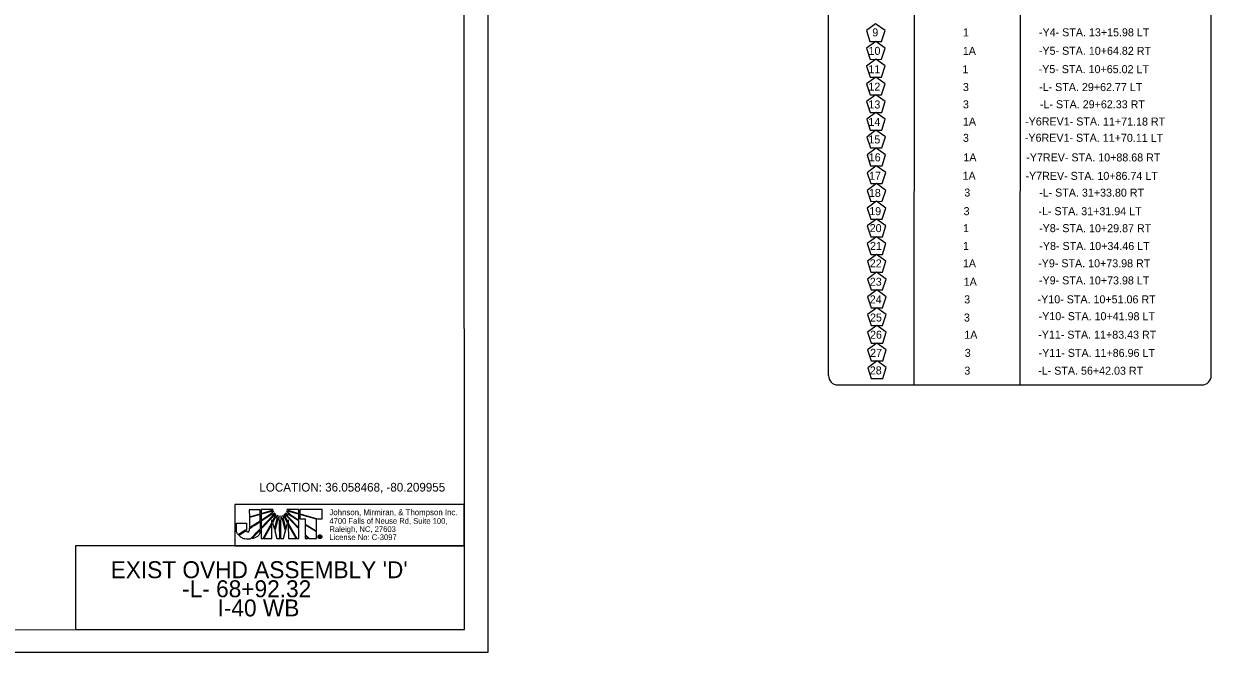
# Model space of a CAD drawing. Extents: x 1726582 to 1728895, y 538986 to 541550.
# Drawn here: x 1727860 to 1728895, y 538986 to 539534 of the extents above; entities that cross this region are included whole.
import ezdxf

# ---------------------------------------------------------------- set-up
doc = ezdxf.new("R2010")
doc.units = 0
for name, color, linetype in [('Default', 7, 'Continuous'), ('DEV BORDER CELL', 7, 'Continuous'), ('GSDIMS', 7, 'Continuous'), ('GSSHT', 7, 'Continuous'), ('Old_Level_7', 7, 'Continuous'), ('Sheet Plot Border Outside CELL', 7, 'Continuous'), ('Sheet Sticker Exception Certification CELL', 7, 'Continuous'), ('Sheet Title CELL', 7, 'Continuous')]:
    doc.layers.add(name, color=color, linetype=linetype)

msp = doc.modelspace()

# ---------------------------------------------------------------- linework, layer by layer
at = {"layer": 'Default'}
for p, q in [((1728636.1, 539699.3), (1728636, 539218.9)), ((1728728.5, 539699.3), (1728728.4, 539218.9)), ((1728066, 539110.2), (1728056.6, 539110.2)), ((1728056.6, 539110.2), (1728056.7, 539104)), ((1728056.7, 539104), (1728066, 539106.6)), ((1728066, 539105.9), (1728056.7, 539103.3)), ((1728066, 539106.6), (1728066, 539110.2)), ((1728066, 539100.5), (1728066, 539105.9)), ((1728077.5, 539110.3), (1728067, 539110.3)), ((1728067, 539110.3), (1728067, 539106.9)), ((1728067, 539106.9), (1728074.8, 539109.1)), ((1728074.8, 539108.4), (1728067, 539106.2)), ((1728067, 539106.2), (1728067, 539101.1)), ((1728067, 539101.1), (1728074, 539105.6)), ((1728075.1, 539105.5), (1728067, 539100.3)), ((1728067, 539094.5), (1728076.9, 539104.8)), ((1728077.3, 539104.3), (1728067, 539093.5)), ((1728074, 539105.6), (1728077.9, 539108.8)), ((1728074.8, 539109.1), (1728077.5, 539110.3)), ((1728077.9, 539108.8), (1728074.8, 539108.4)), ((1728078.7, 539107.3), (1728075.1, 539105.5)), ((1728076.9, 539104.8), (1728078.7, 539107.3)), ((1728079.7, 539106.2), (1728077.3, 539104.3)), ((1728078.6, 539103.2), (1728079.7, 539106.2)), ((1728081.1, 539105.3), (1728079.2, 539103)), ((1728080.8, 539102.5), (1728081.1, 539105.3)), ((1728082.6, 539104.9), (1728081.4, 539101.9)), ((1728083, 539097.5), (1728082.6, 539104.9)), ((1728084.2, 539104.9), (1728083.7, 539097.5)), ((1728085.4, 539101.9), (1728084.2, 539104.9)), ((1728085.7, 539105.3), (1728086, 539102.4)), ((1728087.5, 539103), (1728085.7, 539105.3)), ((1728087, 539106.2), (1728088.2, 539103.2)), ((1728089.5, 539104.3), (1728087, 539106.2)), ((1728088.1, 539107.3), (1728089.9, 539104.7)), ((1728091.7, 539105.5), (1728088.1, 539107.3)), ((1728088.9, 539108.8), (1728092.8, 539105.6)), ((1728091.8, 539108.4), (1728088.9, 539108.8)), ((1728099.8, 539110.3), (1728089.4, 539110.3)), ((1728089.4, 539110.3), (1728092.1, 539109.1)), ((1728099.8, 539093.4), (1728089.5, 539104.3)), ((1728089.9, 539104.7), (1728099.8, 539094.4)), ((1728099.8, 539100.4), (1728091.7, 539105.5)), ((1728099.8, 539106.2), (1728091.8, 539108.4)), ((1728092.1, 539109.1), (1728099.8, 539106.9)), ((1728092.8, 539105.6), (1728099.8, 539101.2)), ((1728099.8, 539106.9), (1728099.8, 539110.3)), ((1728099.8, 539101.2), (1728099.8, 539106.2)), ((1728120.2, 539110.3), (1728100.6, 539110.3)), ((1728100.6, 539110.3), (1728100.6, 539106.7)), ((1728100.6, 539106.7), (1728100.6, 539106.6)), ((1728100.6, 539106.6), (1728116.1, 539102.3)), ((1728100.6, 539106), (1728100.6, 539106)), ((1728100.6, 539106), (1728100.6, 539102.2)), ((1728115.1, 539101.9), (1728100.6, 539106)), ((1728120.2, 539102.3), (1728120.2, 539110.3)), ((1728056.7, 539103.3), (1728056.7, 539094.6)), ((1728056.7, 539094.6), (1728066, 539100.5)), ((1728067, 539100.3), (1728067, 539094.5)), ((1728067, 539093.5), (1728067, 539085)), ((1728068.6, 539085), (1728076.2, 539098.8)), ((1728076.2, 539097.5), (1728069.3, 539085)), ((1728076.2, 539098.8), (1728076.2, 539101.3)), ((1728076.2, 539101.3), (1728076.6, 539099.6)), ((1728076.3, 539085), (1728076.2, 539097.5)), ((1728076.6, 539099.6), (1728078.6, 539103.2)), ((1728079.2, 539103), (1728076.9, 539098.7)), ((1728076.9, 539098.7), (1728078.4, 539093.1)), ((1728078.4, 539093.1), (1728080.8, 539102.5)), ((1728081.4, 539101.9), (1728078.7, 539091.8)), ((1728083.1, 539085.1), (1728083, 539097.5)), ((1728083.7, 539097.5), (1728083.7, 539085.1)), ((1728088.1, 539091.7), (1728085.4, 539101.9)), ((1728086, 539102.4), (1728088.4, 539092.9)), ((1728089.9, 539098.6), (1728087.5, 539103)), ((1728088.2, 539103.2), (1728090.2, 539099.5)), ((1728088.4, 539092.9), (1728089.9, 539098.6)), ((1728090.2, 539099.5), (1728090.6, 539101.3)), ((1728090.6, 539101.3), (1728090.6, 539098.6)), ((1728090.6, 539098.6), (1728098.1, 539085)), ((1728097.4, 539085.1), (1728090.6, 539097.2)), ((1728090.6, 539097.2), (1728090.7, 539085.1)), ((1728099.8, 539094.4), (1728099.8, 539100.4)), ((1728099.8, 539085), (1728099.8, 539093.4)), ((1728100.6, 539102.2), (1728105.4, 539102.2)), ((1728105.4, 539102.2), (1728105.4, 539097.7)), ((1728105.4, 539097.7), (1728115.1, 539091.6)), ((1728105.4, 539096.9), (1728105.4, 539088.6)), ((1728115.1, 539090.9), (1728105.4, 539096.9)), ((1728115.1, 539091.6), (1728115.1, 539101.9)), ((1728116.1, 539102.3), (1728120.2, 539102.3)), ((1728067, 539085), (1728068.6, 539085)), ((1728069.3, 539085), (1728076.3, 539085)), ((1728078.7, 539091.8), (1728080.5, 539085.1)), ((1728080.5, 539085.1), (1728083.1, 539085.1)), ((1728083.7, 539085.1), (1728086.3, 539085.1)), ((1728086.3, 539085.1), (1728088.1, 539091.7)), ((1728090.7, 539085.1), (1728097.4, 539085.1)), ((1728098.1, 539085), (1728099.8, 539085)), ((1728105.4, 539088.6), (1728108.7, 539085)), ((1728107.8, 539085), (1728105.4, 539087.7)), ((1728105.4, 539087.7), (1728105.4, 539085)), ((1728105.4, 539085), (1728107.8, 539085)), ((1728108.7, 539085), (1728115.1, 539085)), ((1728115.1, 539085), (1728115.1, 539090.9)), ((1728117.5, 539085.9), (1728117.5, 539087.4)), ((1728117.5, 539087.4), (1728118.1, 539087.4)), ((1728117.9, 539085.9), (1728117.5, 539085.9)), ((1728118.1, 539087.1), (1728117.9, 539087.1)), ((1728117.9, 539087.1), (1728117.9, 539086.8)), ((1728117.9, 539086.8), (1728118.1, 539086.8)), ((1728118.1, 539086.5), (1728117.9, 539086.5)), ((1728117.9, 539086.5), (1728117.9, 539085.9)), ((1728118.1, 539088.2), (1728118.1, 539087.9)), ((1728118.1, 539087.9), (1728118.1, 539088.2)), ((1728118.1, 539087.4), (1728118.1, 539087.1)), ((1728118.1, 539087.1), (1728118.1, 539087.4)), ((1728118.1, 539087.4), (1728118.2, 539087.4)), ((1728118.2, 539087.1), (1728118.1, 539087.1)), ((1728118.1, 539086.8), (1728118.1, 539086.5)), ((1728118.1, 539086.5), (1728118.1, 539086.8)), ((1728118.1, 539086.8), (1728118.1, 539086.8)), ((1728118.1, 539086.5), (1728118.1, 539086.5)), ((1728118.1, 539085.4), (1728118.1, 539085.1)), ((1728118.1, 539085.1), (1728118.1, 539085.4)), ((1728118.1, 539085.4), (1728118.1, 539085.4)), ((1728118.1, 539085.1), (1728118.1, 539085.1))]:
    msp.add_line(p, q, dxfattribs=at)
for points in [[(1728602.6, 539533.7), (1728594.5, 539527.7), (1728597.6, 539518.2), (1728607.7, 539518.2), (1728610.8, 539527.8)], [(1728602.7, 539518.2), (1728594.6, 539512.3), (1728597.7, 539502.7), (1728607.7, 539502.8), (1728610.8, 539512.3)], [(1728602.7, 539502.8), (1728594.6, 539496.8), (1728597.7, 539487.3), (1728607.8, 539487.3), (1728610.9, 539496.9)], [(1728602.8, 539487.3), (1728594.7, 539481.4), (1728597.8, 539471.8), (1728607.8, 539471.9), (1728610.9, 539481.4)], [(1728602.8, 539471.8), (1728594.7, 539465.9), (1728597.9, 539456.4), (1728607.9, 539456.4), (1728611, 539466)], [(1728602.9, 539456.4), (1728594.8, 539450.5), (1728597.9, 539440.9), (1728607.9, 539440.9), (1728611, 539450.5)], [(1728602.9, 539440.9), (1728594.8, 539435), (1728598, 539425.5), (1728608, 539425.5), (1728611.1, 539435.1)], [(1728603.2, 539425.3), (1728595.1, 539419.4), (1728598.2, 539409.9), (1728608.2, 539409.9), (1728611.3, 539419.5)], [(1728603.2, 539409.9), (1728595.1, 539403.9), (1728598.3, 539394.4), (1728608.3, 539394.4), (1728611.4, 539404)], [(1728603.3, 539394.4), (1728595.2, 539388.5), (1728598.3, 539378.9), (1728608.4, 539379), (1728611.4, 539388.5)], [(1728603.3, 539379), (1728595.2, 539373), (1728598.4, 539363.5), (1728608.4, 539363.5), (1728611.5, 539373.1)], [(1728603.4, 539363.5), (1728595.3, 539357.6), (1728598.4, 539348), (1728608.5, 539348.1), (1728611.5, 539357.6)], [(1728603.4, 539348), (1728595.3, 539342.1), (1728598.5, 539332.6), (1728608.5, 539332.6), (1728611.6, 539342.2)], [(1728603.5, 539332.6), (1728595.4, 539326.7), (1728598.5, 539317.1), (1728608.6, 539317.1), (1728611.6, 539326.7)], [(1728603.5, 539317.1), (1728595.4, 539311.2), (1728598.6, 539301.7), (1728608.6, 539301.7), (1728611.7, 539311.2)], [(1728603.6, 539301.7), (1728595.5, 539295.7), (1728598.6, 539286.2), (1728608.7, 539286.2), (1728611.7, 539295.8)], [(1728603.6, 539286.2), (1728595.5, 539280.3), (1728598.7, 539270.7), (1728608.7, 539270.8), (1728611.8, 539280.3)], [(1728603.7, 539270.8), (1728595.6, 539264.8), (1728598.7, 539255.3), (1728608.8, 539255.3), (1728611.8, 539264.9)], [(1728603.7, 539255.3), (1728595.6, 539249.4), (1728598.8, 539239.8), (1728608.8, 539239.9), (1728611.9, 539249.4)], [(1728603.8, 539239.8), (1728595.7, 539233.9), (1728598.8, 539224.4), (1728608.9, 539224.4), (1728611.9, 539234)], [(1728044, 539078.6), (1728244, 539078.6), (1728244, 539114.7), (1728044, 539114.7)]]:
    msp.add_lwpolyline(points, close=True, dxfattribs=at)
for points in [[(1728056.7, 539104), (1728066, 539106.6), (1728066, 539110.2), (1728056.6, 539110.2), (1728056.7, 539104)], [(1728056.7, 539094.6), (1728066, 539100.5), (1728066, 539105.9), (1728056.7, 539103.3), (1728056.7, 539094.6)], [(1728074.8, 539109.1), (1728077.5, 539110.3), (1728067, 539110.3), (1728067, 539106.9), (1728074.8, 539109.1)], [(1728067, 539106.2), (1728067, 539101.1), (1728074, 539105.6), (1728077.9, 539108.8), (1728074.8, 539108.4), (1728067, 539106.2)], [(1728067, 539100.3), (1728067, 539094.5), (1728076.9, 539104.8), (1728078.7, 539107.3), (1728075.1, 539105.5), (1728067, 539100.3)], [(1728079.7, 539106.2), (1728077.3, 539104.3), (1728067, 539093.5), (1728067, 539085), (1728068.6, 539085), (1728076.2, 539098.8), (1728076.2, 539101.3), (1728076.6, 539099.6), (1728078.6, 539103.2), (1728079.7, 539106.2)], [(1728081.1, 539105.3), (1728079.2, 539103), (1728076.9, 539098.7), (1728078.4, 539093.1), (1728080.8, 539102.5), (1728081.1, 539105.3)], [(1728081.4, 539101.9), (1728078.7, 539091.8), (1728080.5, 539085.1), (1728083.1, 539085.1), (1728083, 539097.5), (1728082.6, 539104.9), (1728081.4, 539101.9)], [(1728084.2, 539104.9), (1728083.7, 539097.5), (1728083.7, 539085.1), (1728086.3, 539085.1), (1728088.1, 539091.7), (1728085.4, 539101.9), (1728084.2, 539104.9)], [(1728085.7, 539105.3), (1728086, 539102.4), (1728088.4, 539092.9), (1728089.9, 539098.6), (1728087.5, 539103), (1728085.7, 539105.3)], [(1728087, 539106.2), (1728088.2, 539103.2), (1728090.2, 539099.5), (1728090.6, 539101.3), (1728090.6, 539098.6), (1728098.1, 539085), (1728099.8, 539085), (1728099.8, 539093.4), (1728089.5, 539104.3), (1728087, 539106.2)], [(1728088.1, 539107.3), (1728089.9, 539104.7), (1728099.8, 539094.4), (1728099.8, 539100.4), (1728091.7, 539105.5), (1728088.1, 539107.3)], [(1728088.9, 539108.8), (1728092.8, 539105.6), (1728099.8, 539101.2), (1728099.8, 539106.2), (1728091.8, 539108.4), (1728088.9, 539108.8)], [(1728092.1, 539109.1), (1728099.8, 539106.9), (1728099.8, 539110.3), (1728089.4, 539110.3), (1728092.1, 539109.1)], [(1728120.2, 539110.3), (1728100.6, 539110.3), (1728100.6, 539106.7), (1728100.6, 539106.6), (1728116.1, 539102.3), (1728120.2, 539102.3), (1728120.2, 539110.3)], [(1728100.6, 539106), (1728100.6, 539106), (1728100.6, 539102.2), (1728105.4, 539102.2), (1728105.4, 539097.7), (1728115.1, 539091.6), (1728115.1, 539101.9), (1728100.6, 539106)], [(1728069.3, 539085), (1728076.3, 539085), (1728076.2, 539097.5), (1728069.3, 539085)], [(1728090.7, 539085.1), (1728097.4, 539085.1), (1728090.6, 539097.2), (1728090.7, 539085.1)], [(1728105.4, 539096.9), (1728105.4, 539088.6), (1728108.7, 539085), (1728115.1, 539085), (1728115.1, 539090.9), (1728105.4, 539096.9), (1728105.4, 539096.9)], [(1728105.4, 539085), (1728105.4, 539085), (1728107.8, 539085), (1728105.4, 539087.7), (1728105.4, 539085)], [(1728118.8, 539086.3), (1728118.8, 539086.2), (1728118.8, 539086.1), (1728118.8, 539086.1), (1728118.8, 539085.9), (1728118.5, 539085.9)]]:
    msp.add_lwpolyline(points, dxfattribs=at)
for points, degree in [([(1728054, 539098.6), (1728054, 539098.6), (1728045.3, 539098.6), (1728045.3, 539098.6), (1728045.3, 539098.6), (1728045.3, 539093.2), (1728045.3, 539093.2), (1728045.3, 539093.2), (1728045.3, 539092.6), (1728045.3, 539092.6), (1728045.3, 539090.9), (1728045.9, 539089.6), (1728046.9, 539088.4), (1728046.9, 539088.4), (1728054, 539092.8), (1728054, 539092.9), (1728054, 539092.9), (1728054, 539098.6), (1728054, 539098.6)], 3), ([(1728055.3, 539090.8), (1728054.8, 539090.8), (1728054.3, 539091.1), (1728054.1, 539092.1), (1728054.1, 539092.1), (1728047.4, 539088), (1728047.4, 539088), (1728049.4, 539085.8), (1728052.7, 539084.5), (1728055.5, 539084.5), (1728056.3, 539084.5), (1728056.8, 539084.6), (1728057.6, 539084.7), (1728057.6, 539084.7), (1728066, 539093.5), (1728066, 539093.5), (1728066, 539093.5), (1728066, 539099.8), (1728066, 539099.8), (1728066, 539099.8), (1728056.7, 539093.8), (1728056.7, 539093.8), (1728056.7, 539091.4), (1728056.1, 539090.8), (1728055.3, 539090.8)], 3), ([(1728055.3, 539090.8), (1728054.8, 539090.8), (1728054.3, 539091.1), (1728054.1, 539092.1), (1728054.1, 539092.1), (1728047.4, 539088), (1728047.4, 539088), (1728049.4, 539085.8), (1728052.7, 539084.5), (1728055.5, 539084.5), (1728056.3, 539084.5), (1728056.8, 539084.6), (1728057.6, 539084.7), (1728057.6, 539084.7), (1728066, 539093.5), (1728066, 539093.5), (1728066, 539093.5), (1728066, 539099.8), (1728066, 539099.8), (1728066, 539099.8), (1728056.7, 539093.8), (1728056.7, 539093.8), (1728056.7, 539091.4), (1728056.1, 539090.8), (1728055.3, 539090.8)], 3), ([(1728066, 539092.5), (1728066, 539092.5), (1728058.7, 539084.9), (1728058.7, 539084.9), (1728062.3, 539085.8), (1728065.9, 539088.2), (1728066, 539092.5)], 3), ([(1728118.1, 539085.1), (1728117.7, 539085.1), (1728117.3, 539085.2), (1728117, 539085.5), (1728116.7, 539085.8), (1728116.5, 539086.2), (1728116.5, 539086.6), (1728116.5, 539087.1), (1728116.7, 539087.5), (1728117, 539087.8), (1728117.3, 539088.1), (1728117.7, 539088.2), (1728118.1, 539088.2)], 3), ([(1728118.1, 539087.9), (1728117.8, 539087.9), (1728117.5, 539087.8), (1728117.2, 539087.6), (1728117, 539087.3), (1728116.9, 539087), (1728116.9, 539086.6), (1728116.9, 539086.3), (1728117, 539086), (1728117.2, 539085.7), (1728117.5, 539085.5), (1728117.8, 539085.4), (1728118.1, 539085.4)], 3), ([(1728118.1, 539088.2), (1728118.6, 539088.2), (1728118.9, 539088.1), (1728119.3, 539087.8), (1728119.6, 539087.5), (1728119.7, 539087.1), (1728119.7, 539086.7)], 3), ([(1728118.1, 539085.4), (1728118.5, 539085.4), (1728118.8, 539085.5), (1728119, 539085.7), (1728119.3, 539086), (1728119.4, 539086.3), (1728119.4, 539086.7), (1728119.4, 539087), (1728119.3, 539087.3), (1728119, 539087.6), (1728118.8, 539087.8), (1728118.5, 539087.9), (1728118.1, 539087.9)], 3), ([(1728118.1, 539086.8), (1728118.3, 539086.8), (1728118.5, 539086.8), (1728118.5, 539086.9), (1728118.5, 539087), (1728118.4, 539087.1), (1728118.2, 539087.1)], 3), ([(1728119.7, 539086.7), (1728119.7, 539086.2), (1728119.6, 539085.8), (1728119.3, 539085.5), (1728119, 539085.2), (1728118.6, 539085.1), (1728118.1, 539085.1)], 3), ([(1728118.4, 539086.4), (1728118.3, 539086.5), (1728118.3, 539086.5), (1728118.1, 539086.5)], 2), ([(1728118.2, 539087.4), (1728118.6, 539087.4), (1728118.8, 539087.2), (1728118.8, 539086.9), (1728118.8, 539086.8), (1728118.7, 539086.7), (1728118.6, 539086.6)], 3), ([(1728118.5, 539085.9), (1728118.5, 539086), (1728118.4, 539086.1), (1728118.4, 539086.2), (1728118.4, 539086.3), (1728118.4, 539086.4), (1728118.4, 539086.4)], 3), ([(1728118.6, 539086.6), (1728118.7, 539086.6), (1728118.7, 539086.5), (1728118.8, 539086.3)], 2)]:
    msp.add_open_spline(points, degree=degree, dxfattribs=at)
at = {"layer": 'DEV BORDER CELL'}
msp.add_line((1728264.8, 538986), (1728264.8, 538986), dxfattribs=at)
at = {"layer": 'GSDIMS'}
msp.add_lwpolyline([(1728243.5, 540054.9), (1726744.7, 540054.1), (1726745.3, 539005), (1728244.1, 539005.8)], close=True, dxfattribs=at)
at = {"layer": 'GSSHT'}
msp.add_lwpolyline([(1727905.2, 539005.8), (1728244.1, 539005.8), (1728244.1, 539078.6), (1727905.2, 539078.6)], close=True, dxfattribs=at)
at = {"layer": 'Sheet Plot Border Outside CELL'}
msp.add_lwpolyline([(1728264.8, 540081.9), (1726581.9, 540081.9), (1726581.9, 538986), (1728264.8, 538986)], close=True, dxfattribs=at)
at = {"layer": 'Sheet Title CELL'}
for p, q in [((1728561.5, 539227.1), (1728561.6, 539711.1)), ((1728895.1, 539227.1), (1728895.2, 539711)), ((1728569.7, 539218.9), (1728887, 539218.9))]:
    msp.add_line(p, q, dxfattribs=at)
for centre, start, end in [((1728569.7, 539227.1), 180, 270), ((1728887, 539227.1), 270, 360)]:
    msp.add_arc(centre, 8.18, start, end, dxfattribs=at)

# ---------------------------------------------------------------- texts
at = {"layer": 'Default'}
for s, height, p in [('9', 6.98, (1728599.7, 539522.7)), ('1', 6.98, (1728678.7, 539522.7)), ('-Y4- STA. 13+15.98 LT', 6.978, (1728745, 539522.8)), ('10', 6.98, (1728596.4, 539506.6)), ('1A', 6.98, (1728678.6, 539506.6)), ('-Y5- STA. 10+64.82 RT', 6.978, (1728744.9, 539506.7)), ('11', 6.98, (1728596.3, 539490.6)), ('1', 6.98, (1728678.3, 539490.6)), ('-Y5- STA. 10+65.02 LT', 6.978, (1728744.7, 539490.7)), ('12', 6.98, (1728596.3, 539475.4)), ('3', 6.98, (1728678.7, 539475.1)), ('-L- STA. 29+62.77 LT', 6.978, (1728745.1, 539475.1)), ('13', 6.98, (1728596.3, 539459.9)), ('3', 6.98, (1728678.7, 539460)), ('-L- STA. 29+62.33 RT', 6.978, (1728745.8, 539460.1)), ('14', 6.98, (1728596.3, 539444.7)), ('1A', 6.98, (1728678.7, 539445)), ('-Y6REV1- STA. 11+71.18 RT', 6.978, (1728732.9, 539445.1)), ('15', 6.98, (1728596.3, 539429.4)), ('3', 6.98, (1728678.7, 539430.8)), ('-Y6REV1- STA. 11+70.11 LT', 6.978, (1728732.7, 539430.9)), ('16', 6.98, (1728596.6, 539413.8)), ('1A', 6.98, (1728679.1, 539413.8)), ('-Y7REV- STA. 10+88.68 RT', 6.978, (1728733.9, 539413.8)), ('17', 6.98, (1728596.9, 539397.7)), ('1A', 6.98, (1728678.4, 539397.7)), ('-Y7REV- STA. 10+86.74 LT', 6.978, (1728733.2, 539397.7)), ('18', 6.98, (1728596.7, 539382.8)), ('3', 6.98, (1728679.9, 539383.1)), ('-L- STA. 31+33.80 RT', 6.978, (1728745.1, 539383.1)), ('19', 6.98, (1728597, 539366.9)), ('3', 6.98, (1728679.3, 539366.9)), ('-L- STA. 31+31.94 LT', 6.978, (1728744.5, 539366.9)), ('20', 6.98, (1728597.4, 539352.1)), ('1', 6.98, (1728678.8, 539352.1)), ('-Y8- STA. 10+29.87 RT', 6.978, (1728745.1, 539352.1)), ('21', 6.98, (1728597.7, 539336.6)), ('1', 6.98, (1728678.8, 539336.6)), ('-Y8- STA. 10+34.46 LT', 6.978, (1728745.3, 539336.6)), ('22', 6.98, (1728597.5, 539321.4)), ('1A', 6.98, (1728678.7, 539321.4)), ('-Y9- STA. 10+73.98 RT', 6.978, (1728744.3, 539321.5)), ('23', 6.98, (1728597.5, 539305.4)), ('1A', 6.98, (1728679.4, 539305.4)), ('-Y9- STA. 10+73.98 LT', 6.978, (1728745, 539306.6)), ('24', 6.98, (1728597.5, 539290)), ('3', 6.98, (1728679.8, 539290)), ('-Y10- STA. 10+51.06 RT', 6.978, (1728743.8, 539290.1)), ('25', 6.98, (1728597.7, 539274.2)), ('3', 6.98, (1728679.6, 539274.2)), ('-Y10- STA. 10+41.98 LT', 6.978, (1728744.7, 539275.4)), ('26', 6.98, (1728597.7, 539259.2)), ('1A', 6.98, (1728679.9, 539259.2)), ('-Y11- STA. 11+83.43 RT', 6.978, (1728744.3, 539259.3)), ('27', 6.98, (1728597.8, 539243.4)), ('3', 6.98, (1728680.3, 539243.4)), ('-Y11- STA. 11+86.96 LT', 6.978, (1728744.7, 539243.4)), ('28', 6.98, (1728597.5, 539228.1)), ('3', 6.98, (1728679.9, 539227.9)), ('-L- STA. 56+42.03 RT', 6.978, (1728744.3, 539227.9))]:
    msp.add_text(s, height=height, rotation=359.9462, dxfattribs=at).set_placement(p)
for s, height, p in [('Johnson, Mirmiran, & Thompson Inc.', 5.111, (1728126.4, 539105.4)), ('4700 Falls of Neuse Rd, Suite 100, ', 4.965, (1728126.4, 539097.9)), ('Raleigh, NC, 27603', 4.965, (1728126.4, 539090.8)), ('License No: C-3097', 4.965, (1728126.4, 539083.7))]:
    msp.add_text(s, height=height, dxfattribs=at).set_placement(p)
at = {"layer": 'Old_Level_7'}
msp.add_text('LOCATION: 36.058468, -80.209955', height=7.564, dxfattribs=at).set_placement((1728065.4, 539126))
at = {"layer": 'Sheet Sticker Exception Certification CELL'}
for s, height, p in [("EXIST OVHD ASSEMBLY 'D'", 14.773, (1727935.7, 539050.5)), ('-L- 68+92.32', 14.773, (1727998, 539033.9)), ('I-40 WB', 14.77, (1728028.9, 539017.2))]:
    msp.add_text(s, height=height, dxfattribs=at).set_placement(p)

doc.saveas('drawing.dxf')
